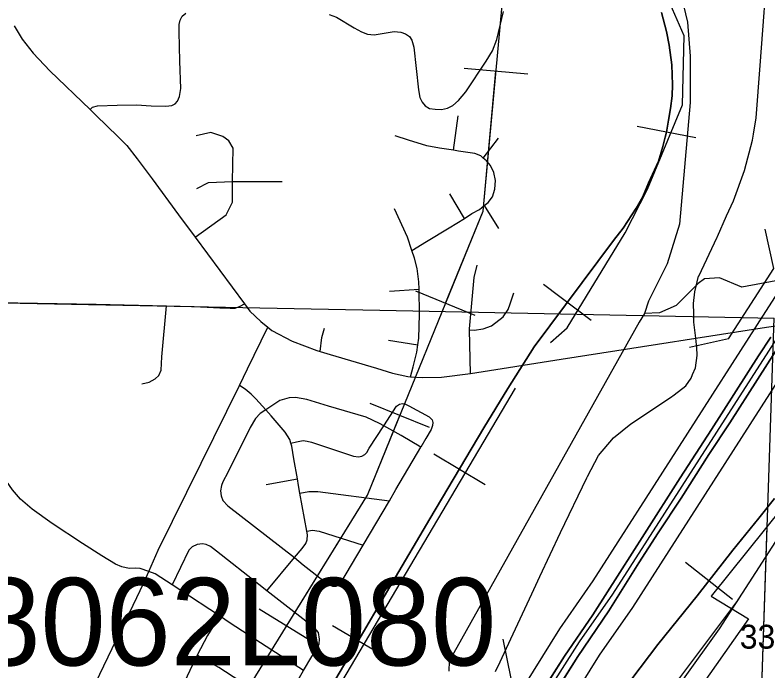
# Model space of a CAD drawing. Extents: x -132.8 to -73.3, y -60 to -26.
# Drawn here: x -120.844 to -119.898, y -49.809 to -48.986 of the extents above; entities that cross this region are included whole.
import ezdxf

# ---------------------------------------------------------------- set-up
doc = ezdxf.new("R2010")
doc.units = 0
for name, color, linetype in [('tdCoCityStreetMajor', 7, 'Continuous'), ('tdCoCityStreetMinor', 7, 'Continuous'), ('tdCoCorpBndry', 7, 'Continuous'), ('tdCoDivCarto', 7, 'Continuous'), ('tdCoHydroRiver', 7, 'Continuous'), ('tdCoInt', 7, 'Continuous'), ('tdCoIntCL', 7, 'Continuous'), ('tdCoIntRte', 7, 'Continuous'), ('tdCoPipe', 7, 'Continuous'), ('tdCoPrimary', 7, 'Continuous'), ('tdCoRRCL', 7, 'Continuous'), ('tdCoSecRdNmbr', 7, 'Continuous'), ('tdCoSecRteCL', 7, 'Continuous'), ('tdCoSectLine', 7, 'Continuous'), ('tdCoSectLinePart', 7, 'Continuous'), ('tdCoStrucDivPri', 7, 'Continuous'), ('tdCoStrucPriMaintName', 7, 'Continuous'), ('tdCoSurfConcUnbanded', 7, 'Continuous')]:
    doc.layers.add(name, color=color, linetype=linetype)

msp = doc.modelspace()

# ---------------------------------------------------------------- linework, layer by layer
at = {"layer": 'tdCoCityStreetMajor'}
for points in [[(-120.84471, -48.99902), (-120.8346, -49.01579), (-120.82079, -49.03354), (-120.80007, -49.05549), (-120.74939, -49.10423), (-120.74212, -49.11123), (-120.71401, -49.1386), (-120.70316, -49.14945), (-120.69033, -49.16622), (-120.67134, -49.19113), (-120.6383, -49.23625), (-120.6175, -49.26439), (-120.55549, -49.34826), (-120.54878, -49.35734), (-120.53497, -49.37041), (-120.52592, -49.37768), (-120.52116, -49.38151), (-120.49551, -49.39507), (-120.46444, -49.40691), (-120.46038, -49.4081), (-120.44776, -49.41181), (-120.38972, -49.42885), (-120.36925, -49.43527), (-120.35001, -49.43946), (-120.34701, -49.43971), (-120.33201, -49.44094), (-120.30784, -49.44044), (-120.27163, -49.43582), (-120.15741, -49.41776), (-120.03641, -49.39895), (-119.98828, -49.39147)], [(-119.98828, -49.39147), (-119.90514, -49.37855), (-119.82992, -49.36696), (-119.79293, -49.3598), (-119.76038, -49.35068), (-119.74114, -49.34575), (-119.72783, -49.34427), (-119.71451, -49.34353), (-119.70218, -49.34427), (-119.68418, -49.34772), (-119.66741, -49.35265), (-119.65301, -49.35498)], [(-120.24004, -49.8099), (-120.23431, -49.79766), (-120.22089, -49.769), (-120.21196, -49.74993), (-120.19444, -49.71251), (-120.18428, -49.6908), (-120.15841, -49.63555), (-120.12525, -49.56658), (-120.12462, -49.56527), (-120.11057, -49.53888), (-120.09183, -49.51669), (-120.06988, -49.49893), (-120.02032, -49.46575), (-120.01538, -49.46243), (-120.00107, -49.45134), (-119.99417, -49.44147), (-119.9923, -49.43697), (-119.98874, -49.4284), (-119.98652, -49.41311), (-119.9871, -49.40278), (-119.98726, -49.3998), (-119.98828, -49.39147)]]:
    msp.add_lwpolyline(points, dxfattribs=at)
at = {"layer": 'tdCoCityStreetMinor'}
for p, q in [((-120.29294, -49.15534), (-120.28685, -49.1119)), ((-120.25532, -49.16519), (-120.23605, -49.14026)), ((-120.57031, -49.19472), (-120.50819, -49.1944)), ((-120.27909, -49.24085), (-120.29746, -49.21005)), ((-120.25407, -49.22475), (-120.23605, -49.2537)), ((-120.37316, -49.33212), (-120.33606, -49.3299)), ((-120.27163, -49.43582), (-120.27283, -49.38092)), ((-120.3744, -49.39402), (-120.3376, -49.3998)), ((-120.52811, -49.57518), (-120.48894, -49.56815)), ((-120.47714, -49.63372), (-120.48568, -49.58611)), ((-120.40638, -49.65132), (-120.37334, -49.59552)), ((-120.52736, -49.70863), (-120.49269, -49.66699))]:
    msp.add_line(p, q, dxfattribs=at)
for points in [[(-119.98828, -49.39147), (-119.99072, -49.37144), (-119.99097, -49.36457), (-119.991, -49.36062), (-119.9911, -49.34769), (-119.98973, -49.33321), (-119.9848, -49.31348), (-119.98473, -49.31334), (-119.96162, -49.26466), (-119.96124, -49.26381), (-119.94959, -49.2377), (-119.94115, -49.21879), (-119.92696, -49.18094), (-119.91701, -49.14246), (-119.91585, -49.13524), (-119.91254, -49.11472), (-119.90758, -49.04886), (-119.90254, -48.98211), (-119.9012, -48.96429), (-119.89637, -48.90302), (-119.89374, -48.86965), (-119.89325, -48.86355), (-119.89182, -48.84537), (-119.8913, -48.83874)], [(-120.44912, -48.98465), (-120.43999, -48.9881), (-120.41755, -49.00142), (-120.40843, -49.0066), (-120.40078, -49.00956), (-120.39265, -49.01054), (-120.38253, -49.00882), (-120.36725, -49.00635), (-120.35911, -49.00684), (-120.35294, -49.00906), (-120.34826, -49.01252), (-120.3453, -49.01695), (-120.34258, -49.02583), (-120.33691, -49.07935), (-120.33494, -49.08896), (-120.33223, -49.09488), (-120.32828, -49.09957), (-120.32286, -49.10277), (-120.3157, -49.10376), (-120.30806, -49.10401), (-120.30041, -49.10253), (-120.29376, -49.09907), (-120.28636, -49.09291), (-120.27723, -49.08206), (-120.25159, -49.04359), (-120.2437, -49.03027), (-120.23827, -49.01621), (-120.23013, -48.98095)], [(-120.74939, -49.10423), (-120.74628, -49.10129), (-120.74011, -49.09957), (-120.71545, -49.09883), (-120.69129, -49.09809), (-120.67254, -49.09957), (-120.6543, -49.10006), (-120.6469, -49.09907), (-120.6427, -49.0971), (-120.6395, -49.09365), (-120.63703, -49.08798), (-120.63531, -49.07762), (-120.63654, -49.04359), (-120.63728, -49.0066), (-120.63728, -48.99723), (-120.63605, -48.9918), (-120.63358, -48.98687), (-120.62914, -48.98317)], [(-120.57031, -49.19472), (-120.56974, -49.15279), (-120.57517, -49.14369), (-120.58266, -49.1379), (-120.59755, -49.1332), (-120.61595, -49.13712)], [(-120.29294, -49.15534), (-120.31028, -49.15284), (-120.32631, -49.14963), (-120.34924, -49.14272), (-120.36626, -49.13705)], [(-120.25532, -49.16519), (-120.25849, -49.16245), (-120.26614, -49.15949), (-120.28636, -49.15629), (-120.29294, -49.15534)], [(-120.25407, -49.22475), (-120.24912, -49.2209), (-120.24394, -49.21375), (-120.24074, -49.20413), (-120.24, -49.19328), (-120.24222, -49.18317), (-120.24616, -49.17454), (-120.25134, -49.16862), (-120.25532, -49.16519)], [(-120.6175, -49.26439), (-120.57836, -49.2366), (-120.57052, -49.22054), (-120.57031, -49.19472)], [(-120.61524, -49.20335), (-120.60066, -49.19576), (-120.57031, -49.19472)], [(-120.27909, -49.24085), (-120.26959, -49.23496), (-120.26022, -49.22953), (-120.25407, -49.22475)], [(-120.34513, -49.28103), (-120.35072, -49.26455), (-120.367, -49.22904)], [(-120.34513, -49.28103), (-120.3268, -49.26973), (-120.2982, -49.25271), (-120.27909, -49.24085)], [(-120.33606, -49.3299), (-120.33617, -49.32053), (-120.33839, -49.304), (-120.34184, -49.29069), (-120.34513, -49.28103)], [(-120.27283, -49.38092), (-120.27271, -49.37957), (-120.26694, -49.31503), (-120.26308, -49.29986)], [(-120.3376, -49.3998), (-120.33642, -49.3913), (-120.33568, -49.36146), (-120.33606, -49.3299)], [(-121.13758, -49.33921), (-121.10172, -49.33964), (-120.9143, -49.34581), (-120.74168, -49.34877), (-120.65337, -49.35089)], [(-120.27283, -49.38092), (-120.26688, -49.38126), (-120.25555, -49.37943), (-120.24488, -49.3757), (-120.23054, -49.36467), (-120.22429, -49.35528), (-120.22155, -49.34806), (-120.21685, -49.33456)], [(-120.68422, -49.44889), (-120.67509, -49.44643), (-120.66769, -49.44223), (-120.66301, -49.43804), (-120.6603, -49.43138), (-120.65906, -49.41486), (-120.65337, -49.35089)], [(-120.65337, -49.35089), (-120.61862, -49.35173), (-120.58631, -49.35321), (-120.57349, -49.3537), (-120.56732, -49.3537), (-120.56067, -49.35099), (-120.55549, -49.34826)], [(-120.56185, -49.45087), (-120.55146, -49.42977), (-120.52592, -49.37768)], [(-120.46038, -49.4081), (-120.45824, -49.39032), (-120.45479, -49.37897)], [(-120.34701, -49.43971), (-120.34332, -49.42755), (-120.33889, -49.40906), (-120.3376, -49.3998)], [(-120.67557, -49.68446), (-120.67555, -49.68441), (-120.66367, -49.65764), (-120.64567, -49.62107), (-120.60991, -49.54839), (-120.56185, -49.45087)], [(-120.52865, -49.48121), (-120.54118, -49.46742), (-120.5471, -49.4615), (-120.55449, -49.45533), (-120.56185, -49.45087)], [(-120.67557, -49.68446), (-120.68642, -49.68043), (-120.69259, -49.68018), (-120.70048, -49.68043), (-120.70936, -49.6787), (-120.71749, -49.675), (-120.73476, -49.66465), (-120.75892, -49.64936), (-120.7969, -49.62396), (-120.82206, -49.60595), (-120.83685, -49.59338), (-120.84672, -49.58203), (-120.85461, -49.57094), (-120.86349, -49.55565), (-120.87335, -49.54332), (-120.88765, -49.53123), (-120.92884, -49.49572), (-120.94043, -49.48635), (-120.953, -49.47796), (-120.96509, -49.4718), (-120.97739, -49.46829)], [(-120.38047, -49.50139), (-120.38589, -49.4984), (-120.40242, -49.49076), (-120.44976, -49.47695), (-120.47714, -49.46857), (-120.49144, -49.46585), (-120.49908, -49.4661), (-120.51092, -49.4698), (-120.52865, -49.48121)], [(-120.38047, -49.50139), (-120.36461, -49.47679), (-120.36066, -49.47432), (-120.35672, -49.47358), (-120.35302, -49.47432), (-120.34907, -49.4763), (-120.32318, -49.49035), (-120.31948, -49.49405), (-120.31874, -49.49726), (-120.31923, -49.5012), (-120.32071, -49.50614), (-120.32737, -49.51723), (-120.33393, -49.52842)], [(-120.52865, -49.48121), (-120.53583, -49.48583), (-120.5415, -49.49224), (-120.54841, -49.50334), (-120.57652, -49.56006), (-120.58244, -49.57189), (-120.58441, -49.57633), (-120.5854, -49.58299), (-120.5849, -49.58916), (-120.58244, -49.59532), (-120.57652, -49.60198), (-120.49269, -49.66699)], [(-120.49705, -49.52317), (-120.49827, -49.51871), (-120.50419, -49.50934), (-120.5217, -49.48887), (-120.52865, -49.48121)], [(-120.49705, -49.52317), (-120.49013, -49.52167), (-120.48174, -49.51995), (-120.47657, -49.52068), (-120.47139, -49.52216), (-120.41837, -49.53967), (-120.41196, -49.54041), (-120.40801, -49.53967), (-120.40406, -49.53745), (-120.40184, -49.53499), (-120.39864, -49.52956), (-120.38047, -49.50139)], [(-120.33393, -49.52842), (-120.35852, -49.51345), (-120.38047, -49.50139)], [(-120.48894, -49.56815), (-120.49358, -49.54288), (-120.49605, -49.52685), (-120.49705, -49.52317)], [(-120.37334, -49.59552), (-120.3651, -49.5816), (-120.33393, -49.52842)], [(-120.48568, -49.58611), (-120.48742, -49.57642), (-120.48894, -49.56815)], [(-120.48568, -49.58611), (-120.47459, -49.58406), (-120.46325, -49.58406), (-120.37334, -49.59552)], [(-120.49269, -49.66699), (-120.48298, -49.65533), (-120.47829, -49.64941), (-120.47657, -49.64448), (-120.47632, -49.63832), (-120.47714, -49.63372)], [(-120.47714, -49.63372), (-120.47015, -49.63264), (-120.46152, -49.63388), (-120.40638, -49.65132)], [(-120.52736, -49.70863), (-120.53748, -49.70071), (-120.59075, -49.65878), (-120.59814, -49.65311), (-120.60357, -49.6504), (-120.60801, -49.64966), (-120.61491, -49.6504), (-120.62132, -49.65336), (-120.62527, -49.65755), (-120.64617, -49.70123)], [(-120.49269, -49.66699), (-120.48152, -49.67582), (-120.45314, -49.69824), (-120.44919, -49.7012), (-120.445, -49.70293), (-120.44023, -49.70269), (-120.44007, -49.70268), (-120.43563, -49.70071), (-120.40638, -49.65132)], [(-120.77349, -49.88797), (-120.76256, -49.86651), (-120.71644, -49.77083), (-120.70366, -49.74417), (-120.68216, -49.69932), (-120.67557, -49.68446)], [(-120.64617, -49.70123), (-120.66769, -49.68739), (-120.67557, -49.68446)], [(-120.587, -49.74018), (-120.63661, -49.70737), (-120.64617, -49.70123)], [(-120.48106, -49.80884), (-120.47065, -49.79097), (-120.46399, -49.7811), (-120.46177, -49.77518), (-120.46128, -49.76926), (-120.46251, -49.76088), (-120.4672, -49.7557), (-120.52736, -49.70863)], [(-119.97848, -50.06793), (-119.98392, -50.07546), (-119.99231, -50.08188), (-120.00193, -50.08484), (-120.02067, -50.08533), (-120.11043, -50.08311), (-120.11956, -50.08114), (-120.12671, -50.07744), (-120.13238, -50.07127), (-120.13633, -50.06338), (-120.13756, -50.05549), (-120.13657, -50.01948), (-120.13485, -50.00641), (-120.13213, -49.99976), (-120.1272, -49.9926), (-120.09687, -49.95463), (-120.07089, -49.92206), (-120.06154, -49.90958), (-120.05283, -49.89564), (-120.04608, -49.88257), (-120.03454, -49.86145), (-120.02409, -49.8425), (-120.01581, -49.82812), (-119.94318, -49.73103)], [(-120.587, -49.74018), (-120.59173, -49.7483), (-120.60184, -49.76483), (-120.61476, -49.78963)], [(-120.48106, -49.80884), (-120.52835, -49.77864), (-120.57324, -49.74929), (-120.587, -49.74018)], [(-120.61476, -49.78963), (-120.61738, -49.79466), (-120.63094, -49.82302), (-120.63316, -49.82796), (-120.63513, -49.83264), (-120.63686, -49.83807), (-120.63711, -49.84275)], [(-120.50852, -49.85659), (-120.58754, -49.80478), (-120.61476, -49.78963)], [(-120.50852, -49.85659), (-120.49679, -49.83585), (-120.48106, -49.80884)]]:
    msp.add_lwpolyline(points, dxfattribs=at)
at = {"layer": 'tdCoCorpBndry'}
msp.add_lwpolyline([(-119.83422, -49.5474), (-119.96898, -49.71539), (-119.92205, -49.74386), (-120.05185, -49.92842), (-119.98652, -49.97118), (-119.94726, -49.90163), (-119.92449, -49.91499), (-119.90849, -49.93984), (-119.9319, -49.98429), (-119.90531, -50.0017), (-119.91598, -50.01735), (-119.90808, -50.02258), (-119.89742, -50.00693)], dxfattribs=at)
at = {"layer": 'tdCoDivCarto'}
for p, q in [((-119.91055, -49.44307), (-119.87569, -49.38896)), ((-119.89392, -49.39021), (-119.90948, -49.41364)), ((-119.90948, -49.41364), (-119.96867, -49.50587)), ((-119.94532, -49.49757), (-119.91055, -49.44307)), ((-119.97147, -49.53727), (-119.94532, -49.49757)), ((-119.96867, -49.50587), (-120.00788, -49.56678)), ((-120.00648, -49.59226), (-119.97147, -49.53727)), ((-120.00788, -49.56678), (-120.05276, -49.63706)), ((-120.03534, -49.63567), (-120.00648, -49.59226)), ((-120.0595, -49.67364), (-120.03534, -49.63567)), ((-120.05276, -49.63706), (-120.08384, -49.68565)), ((-120.09723, -49.73382), (-120.0595, -49.67364)), ((-120.08384, -49.68565), (-120.11787, -49.73867)), ((-120.11787, -49.73867), (-120.15338, -49.79095)), ((-120.1362, -49.79128), (-120.09723, -49.73382)), ((-120.15338, -49.79095), (-120.18223, -49.83583)), ((-120.16505, -49.8369), (-120.1362, -49.79128))]:
    msp.add_line(p, q, dxfattribs=at)
for points in [[(-120.37202, -50.15526), (-120.37121, -50.15428), (-120.35297, -50.12937), (-120.3362, -50.10422), (-120.31055, -50.06402), (-120.26468, -49.99177), (-120.23607, -49.94787), (-120.20633, -49.90252), (-120.19612, -49.88696), (-120.18882, -49.87519), (-120.16505, -49.8369), (-120.1362, -49.79128), (-120.09723, -49.73382), (-120.0595, -49.67364), (-120.03534, -49.63567), (-120.00648, -49.59226), (-119.97147, -49.53727), (-119.94532, -49.49757), (-119.91055, -49.44307), (-119.87569, -49.38896)], [(-120.37202, -50.15526), (-120.37121, -50.15428), (-120.35297, -50.12937), (-120.3362, -50.10422), (-120.31055, -50.06402), (-120.26468, -49.99177), (-120.23607, -49.94787), (-120.20633, -49.90252), (-120.19612, -49.88696), (-120.18882, -49.87519), (-120.16505, -49.8369), (-120.1362, -49.79128), (-120.09723, -49.73382), (-120.0595, -49.67364), (-120.03534, -49.63567), (-120.00648, -49.59226), (-119.97147, -49.53727), (-119.94532, -49.49757), (-119.91055, -49.44307), (-119.87569, -49.38896)], [(-120.37121, -50.15428), (-120.35297, -50.12937), (-120.3362, -50.10422), (-120.31055, -50.06402), (-120.26468, -49.99177), (-120.23607, -49.94787), (-120.20633, -49.90252), (-120.19612, -49.88696), (-120.18882, -49.87519), (-120.16505, -49.8369), (-120.1362, -49.79128), (-120.09723, -49.73382), (-120.0595, -49.67364), (-120.03534, -49.63567), (-120.00648, -49.59226), (-119.97147, -49.53727), (-119.94532, -49.49757), (-119.91055, -49.44307), (-119.87569, -49.38896)], [(-119.89392, -49.39021), (-119.90948, -49.41364), (-119.96867, -49.50587), (-120.00788, -49.56678), (-120.05276, -49.63706), (-120.08384, -49.68565), (-120.11787, -49.73867), (-120.15338, -49.79095), (-120.18223, -49.83583)], [(-119.89392, -49.39021), (-119.90948, -49.41364), (-119.96867, -49.50587), (-120.00788, -49.56678), (-120.05276, -49.63706), (-120.08384, -49.68565), (-120.11787, -49.73867), (-120.15338, -49.79095), (-120.18223, -49.83583)], [(-119.89392, -49.39021), (-119.90948, -49.41364), (-119.96867, -49.50587), (-120.00788, -49.56678), (-120.05276, -49.63706), (-120.08384, -49.68565), (-120.11787, -49.73867), (-120.15338, -49.79095), (-120.18223, -49.83583)]]:
    msp.add_lwpolyline(points, dxfattribs=at)
at = {"layer": 'tdCoHydroRiver'}
for points in [[(-120.00589, -48.96412), (-119.99881, -48.99429), (-119.99523, -49.03698), (-119.99522, -49.09536), (-120.0088, -49.24803), (-120.02436, -49.2981), (-120.04771, -49.3448), (-120.05287, -49.36043)], [(-119.59469, -49.4028), (-119.61507, -49.39751), (-119.62727, -49.38141), (-119.64219, -49.34945), (-119.66376, -49.32993), (-119.69816, -49.31796), (-119.78334, -49.31566), (-119.8876, -49.31915), (-119.93044, -49.32746), (-119.95854, -49.31565), (-119.9775, -49.31672), (-119.98556, -49.32281), (-120.01314, -49.35046), (-120.0339, -49.35936), (-120.05287, -49.36043)], [(-120.05287, -49.36043), (-120.05947, -49.3713), (-120.29823, -49.79713), (-120.29856, -49.80974)]]:
    msp.add_lwpolyline(points, dxfattribs=at)
at = {"layer": 'tdCoInt'}
for points in [[(-120.23496, -49.87826), (-120.1593, -49.75622), (-120.11744, -49.69617), (-119.90023, -49.35773), (-119.76581, -49.1489)], [(-120.18498, -49.91147), (-120.10937, -49.78952), (-120.06756, -49.72955), (-119.8496, -49.38993)]]:
    msp.add_lwpolyline(points, dxfattribs=at)
at = {"layer": 'tdCoIntCL'}
msp.add_lwpolyline([(-120.82479, -50.51314), (-120.77021, -50.48549), (-120.74527, -50.47349), (-120.71045, -50.45601), (-120.6848, -50.4454), (-120.65959, -50.43304), (-120.64056, -50.42167), (-120.61264, -50.40314), (-120.58407, -50.38025), (-120.53835, -50.33521), (-120.49535, -50.28607), (-120.44553, -50.22941), (-120.39094, -50.16732), (-120.37837, -50.15034), (-120.35408, -50.1175), (-120.31314, -50.05267), (-120.20997, -49.89486), (-120.20403, -49.88607), (-120.18586, -49.85366), (-120.13434, -49.77287), (-120.0925, -49.71286), (-119.87491, -49.37383)], dxfattribs=at)
at = {"layer": 'tdCoIntRte'}
for points in [[(-120.16543, -49.8369), (-120.13658, -49.79128), (-120.09761, -49.73382), (-120.05988, -49.67364), (-120.03571, -49.63567), (-120.00686, -49.59226), (-119.97184, -49.53727), (-119.9457, -49.49757), (-119.91093, -49.44307), (-119.87606, -49.38896)], [(-120.16543, -49.8369), (-120.13658, -49.79128), (-120.09761, -49.73382), (-120.05988, -49.67364), (-120.03571, -49.63567), (-120.00686, -49.59226), (-119.97184, -49.53727), (-119.9457, -49.49757), (-119.91093, -49.44307), (-119.87606, -49.38896)], [(-119.8943, -49.39021), (-119.90986, -49.41364), (-119.96905, -49.50587), (-120.00826, -49.56678), (-120.05314, -49.63706), (-120.08421, -49.68565), (-120.11825, -49.73867), (-120.15376, -49.79095), (-120.18261, -49.83583)], [(-119.8943, -49.39021), (-119.90986, -49.41364), (-119.96905, -49.50587), (-120.00826, -49.56678), (-120.05314, -49.63706), (-120.08421, -49.68565), (-120.11825, -49.73867), (-120.15376, -49.79095), (-120.18261, -49.83583)]]:
    msp.add_lwpolyline(points, dxfattribs=at)
at = {"layer": 'tdCoPipe'}
for p, q in [((-120.19926, -49.05988), (-120.27958, -49.05245)), ((-120.26549, -49.36271), (-120.34006, -49.33234)), ((-120.3229, -49.50366), (-120.39761, -49.47322)), ((-120.46842, -49.77409), (-120.5369, -49.73173))]:
    msp.add_line(p, q, dxfattribs=at)
for points in [[(-119.79665, -53.49603), (-120.03098, -53.27088), (-120.31929, -53.03672), (-120.68529, -52.8785), (-121.0012, -52.82656), (-121.49047, -52.40565), (-121.39982, -51.55717), (-121.23691, -50.91275), (-120.91445, -50.41851), (-120.40095, -49.58835), (-120.25565, -49.23166), (-120.19476, -48.57334), (-120.22335, -47.97882), (-119.95841, -47.76157), (-119.94709, -47.38436)], [(-120.30284, -49.3475), (-120.25565, -49.23166), (-120.23941, -49.05616)], [(-120.50272, -49.75287), (-120.40095, -49.58835), (-120.36025, -49.48844)]]:
    msp.add_lwpolyline(points, dxfattribs=at)
at = {"layer": 'tdCoPrimary'}
for points in [[(-120.37121, -50.15428), (-120.35297, -50.12937), (-120.3362, -50.10422), (-120.31055, -50.06402), (-120.26468, -49.99177), (-120.23607, -49.94787), (-120.20633, -49.90252), (-120.19612, -49.88696), (-120.18882, -49.87519), (-120.16505, -49.8369), (-120.1362, -49.79128), (-120.09723, -49.73382), (-120.0595, -49.67364), (-120.03534, -49.63567), (-120.00648, -49.59226), (-119.97147, -49.53727), (-119.94532, -49.49757), (-119.91055, -49.44307), (-119.87569, -49.38896)], [(-120.37121, -50.15428), (-120.35297, -50.12937), (-120.3362, -50.10422), (-120.31055, -50.06402), (-120.26468, -49.99177), (-120.23607, -49.94787), (-120.20633, -49.90252), (-120.19612, -49.88696), (-120.18882, -49.87519), (-120.16505, -49.8369), (-120.1362, -49.79128), (-120.09723, -49.73382), (-120.0595, -49.67364), (-120.03534, -49.63567), (-120.00648, -49.59226), (-119.97147, -49.53727), (-119.94532, -49.49757), (-119.91055, -49.44307), (-119.87569, -49.38896)], [(-120.16505, -49.8369), (-120.1362, -49.79128), (-120.09723, -49.73382), (-120.0595, -49.67364), (-120.03534, -49.63567), (-120.00648, -49.59226), (-119.97147, -49.53727), (-119.94532, -49.49757), (-119.91055, -49.44307), (-119.87569, -49.38896)], [(-119.89392, -49.39021), (-119.90948, -49.41364), (-119.96867, -49.50587), (-120.00788, -49.56678), (-120.05276, -49.63706), (-120.08384, -49.68565), (-120.11787, -49.73867), (-120.15338, -49.79095), (-120.18223, -49.83583)], [(-119.89392, -49.39021), (-119.90948, -49.41364), (-119.96867, -49.50587), (-120.00788, -49.56678), (-120.05276, -49.63706), (-120.08384, -49.68565), (-120.11787, -49.73867), (-120.15338, -49.79095), (-120.18223, -49.83583)], [(-119.89392, -49.39021), (-119.90948, -49.41364), (-119.96867, -49.50587), (-120.00788, -49.56678), (-120.05276, -49.63706), (-120.08384, -49.68565), (-120.11787, -49.73867), (-120.15338, -49.79095), (-120.18223, -49.83583)]]:
    msp.add_lwpolyline(points, dxfattribs=at)
at = {"layer": 'tdCoRRCL'}
for p, q in [((-120.06212, -49.12499), (-119.98848, -49.1392)), ((-120.17971, -49.32365), (-120.11962, -49.36854)), ((-120.31762, -49.53655), (-120.2532, -49.57496)), ((-120.00128, -49.67281), (-119.94238, -49.71924)), ((-120.44466, -49.75219), (-120.37996, -49.79012))]:
    msp.add_line(p, q, dxfattribs=at)
for points in [[(-120.17079, -49.39683), (-120.14979, -49.37845), (-120.07723, -49.25887), (-120.04898, -49.20439), (-120.00518, -49.09825), (-120.00292, -49.01154), (-120.01783, -48.97802), (-120.11329, -48.70416), (-120.11824, -48.65197), (-120.11523, -48.59683), (-120.09903, -48.51995), (-119.98769, -48.12372)], [(-120.90014, -50.91758), (-120.80482, -50.8333), (-120.69913, -50.71459), (-120.38749, -50.3671), (-120.27515, -50.19914), (-119.95857, -49.75638), (-119.76019, -49.4486), (-119.624, -49.31017), (-119.6013, -49.2871), (-119.53026, -49.22585), (-119.46076, -49.16298), (-119.40286, -49.1219), (-119.33353, -49.06534), (-119.1714, -48.90077), (-118.98751, -48.68786), (-118.88892, -48.59894), (-118.66302, -48.40922), (-118.39059, -48.19074)], [(-120.50194, -49.92279), (-120.41884, -49.78228), (-120.36984, -49.69869), (-120.32264, -49.61818), (-120.25448, -49.50389), (-120.22459, -49.45461), (-120.19157, -49.40218), (-120.09169, -49.26849), (-120.07963, -49.25302), (-120.06338, -49.22812), (-120.05473, -49.21344), (-120.04765, -49.1964), (-120.03533, -49.16887), (-120.02982, -49.15079), (-120.0269, -49.13873), (-120.02537, -49.13244), (-120.02248, -49.1175), (-120.02012, -49.10308), (-120.01803, -49.08709), (-120.01777, -49.07319), (-120.01855, -49.04803), (-120.02196, -49.02339), (-120.02511, -49.00609), (-120.0314, -48.98223)], [(-120.0314, -48.98223), (-120.02511, -49.00609), (-120.02196, -49.02339), (-120.01855, -49.04803), (-120.01777, -49.07319), (-120.01803, -49.08709), (-120.02012, -49.10308), (-120.02248, -49.1175), (-120.02537, -49.13244), (-120.0269, -49.13873), (-120.02982, -49.15079), (-120.03533, -49.16887), (-120.04765, -49.1964), (-120.05473, -49.21344), (-120.06338, -49.22812), (-120.07963, -49.25302), (-120.09169, -49.26849), (-120.19157, -49.40218), (-120.22459, -49.45461), (-120.25448, -49.50389), (-120.32264, -49.61818), (-120.36984, -49.69869), (-120.41884, -49.78228), (-120.50194, -49.92279)], [(-120.73756, -50.43274), (-120.69929, -50.29648), (-120.66893, -50.22155), (-120.2149, -49.45405)], [(-120.06868, -49.81919), (-120.03593, -49.77619), (-119.98671, -49.71489), (-119.9417, -49.6578), (-119.90915, -49.61729), (-119.88936, -49.59266)], [(-119.88936, -49.59266), (-119.90915, -49.61729), (-119.9417, -49.6578), (-119.98671, -49.71489), (-120.03593, -49.77619), (-120.06868, -49.81919)]]:
    msp.add_lwpolyline(points, dxfattribs=at)
at = {"layer": 'tdCoSecRteCL'}
msp.add_line((-119.94318, -49.73103), (-119.93436, -49.71923), dxfattribs=at)
at = {"layer": 'tdCoSectLine'}
for points in [[(-120.88076, -49.34639), (-120.38523, -49.35621), (-119.8897, -49.36604)], [(-119.92398, -50.36772), (-119.90684, -49.86688), (-119.8897, -49.36604)]]:
    msp.add_lwpolyline(points, dxfattribs=at)
at = {"layer": 'tdCoSectLinePart'}
msp.add_lwpolyline([(-119.90931, -49.93915), (-119.90684, -49.86688), (-119.89863, -49.62722)], dxfattribs=at)
at = {"layer": 'tdCoStrucDivPri'}
for p, q in [((-119.89027, -49.30376), (-119.90102, -49.2545)), ((-119.94706, -49.39224), (-119.89027, -49.30376)), ((-119.94706, -49.39224), (-119.9963, -49.40296)), ((-120.22038, -49.81884), (-120.23036, -49.76943))]:
    msp.add_line(p, q, dxfattribs=at)
at = {"layer": 'tdCoSurfConcUnbanded'}
msp.add_line((-119.94318, -49.73103), (-119.93436, -49.71923), dxfattribs=at)

# ---------------------------------------------------------------- texts
at = {"layer": 'tdCoSecRdNmbr'}
msp.add_text('3308', height=0.03, rotation=359.91047, dxfattribs=at).set_placement((-119.93308, -49.78127))
at = {"layer": 'tdCoStrucPriMaintName'}
msp.add_text('78062L080', height=0.11, dxfattribs=at).set_placement((-120.97535, -49.80246))

doc.saveas('drawing.dxf')
